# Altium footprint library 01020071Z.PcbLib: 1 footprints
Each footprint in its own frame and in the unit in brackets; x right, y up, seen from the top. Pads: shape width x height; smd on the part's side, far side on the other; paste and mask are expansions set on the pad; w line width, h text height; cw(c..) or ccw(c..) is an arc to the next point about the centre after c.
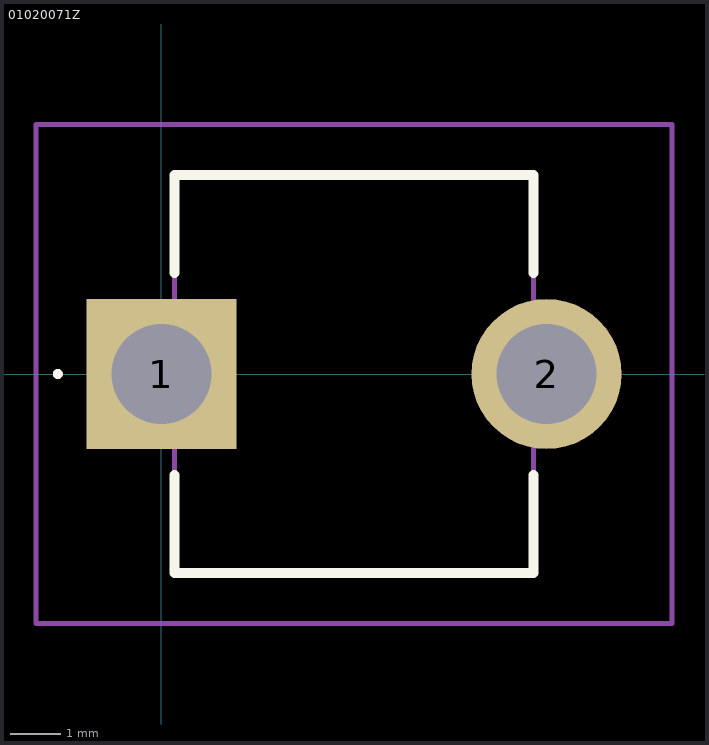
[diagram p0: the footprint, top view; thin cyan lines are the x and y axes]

## 01020071Z [mm]
pads (2):
  rect 2.97x2.97 hole 1.98: 1(0,0)
  round 2.97 hole 1.98: 2(7.62,0)
Top Overlay:
  lines w0.1: -2.1,0 -2.1,0 ; -2.1,0 ccw(c-2.05,0) -2,0 ; -2.1,0 cw(c-2.05,0) -2,0 ; -2,0 -2,0
  lines w0.2: 0.255,-2 0.255,-3.935 7.365,-3.935 7.365,-2 ; 0.255,2 0.255,3.935 7.365,3.935 7.365,2
Mechanical 15:
  lines w0.1: 0.255,-3.935 7.365,-3.935 7.365,3.935 0.255,3.935 0.255,-3.935
Mechanical 20:
  lines w0.1: -2.485,-4.935 10.105,-4.935 10.105,4.935 -2.485,4.935 -2.485,-4.935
